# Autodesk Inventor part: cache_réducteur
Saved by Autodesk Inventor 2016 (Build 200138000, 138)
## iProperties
Created: 2013-08
Part Number: cache_réducteur
Material: Générique
Document SubType Name: Modeling
Designer: hilarion
Density: 1 g/cm^3
Appearance: Par défaut
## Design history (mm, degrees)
node "cache_réducteur1"
node "cache_réducteur"
node "Base1"
